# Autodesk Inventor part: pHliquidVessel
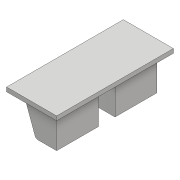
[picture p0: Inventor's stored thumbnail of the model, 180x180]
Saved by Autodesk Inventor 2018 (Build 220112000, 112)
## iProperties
Created: 2018-05
Part Number: pHliquidVessel
Material: Generic
Document SubType Name: Modeling
Designer: arivu
Density: 1 g/cm^3
Appearance: Default
Author: arivu
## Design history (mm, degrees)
derived "WaterTank.ipt"
sketch "Sketch1"
  geometry: L1 (0, 0)-(-22.2, 0) reference; L2 (-25.959, 120)-(-40, 120) reference; L3 (0, 0)-(-40, 0); L4 (-40, 0)-(-40, 120); L5 (-40, 120)-(0, 120); L6 (0, 120)-(0, 0); 1 further point
  constraints: 8 end point, 2 parallel, 1 horizontal, 1 perpendicular
extrude "Extrusion1" new body sketch "Sketch1" distance "d1" = 5; taper "d2" = 0 deg
sketch "Sketch2"
  geometry: L1 (0, 120)-(0, 0) reference; L2 (0, 120)-(-5, 120) reference; L3 (-5, 0)-(-5, 120) reference; L4 (0, 0)-(-5, 0) reference; 1 further point
extrude "Extrusion2" join sketch "Sketch2" distance "d3" = 10; taper "d4" = 0 deg
sketch "Sketch3"
  geometry: L1 (0, 0)-(0, 120) reference; L2 (0, 0)-(5, 0) reference; L3 (5, 120)-(5, 0) reference; L4 (0, 120)-(5, 120) reference; 1 further point
extrude "Extrusion3" join sketch "Sketch3" distance "d5" = 10; taper "d6" = 0 deg
sketch "Sketch4"
  geometry: L1 (0, 0)-(-60, 0) reference; L2 (0, 5)-(0, 0) reference; L3 (0, 5)-(-60, 5) reference; L4 (-60, 0)-(-60, 5) reference; 1 further point
extrude "Extrusion4" join sketch "Sketch4" distance "d7" = 10; taper "d8" = 0 deg
sketch "Sketch5"
  geometry: L1 (-60, 5)-(0, 5) reference; L2 (-60, 0)-(-60, 5) reference; L3 (-60, 0)-(0, 0) reference; L4 (0, 5)-(0, 0) reference; 1 further point
extrude "Extrusion5" join sketch "Sketch5" distance "d9" = 10; taper "d10" = 0 deg
feature "Solid8::WaterTank.ipt" dims "d0" = 10
tag "TaggingFeature1"
body "Solid2"
node "Projected Loop1"
node "Projected Loop2"
node "Projected Loop3"
node "Projected Loop4"
body "Solid1"
